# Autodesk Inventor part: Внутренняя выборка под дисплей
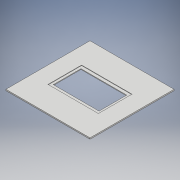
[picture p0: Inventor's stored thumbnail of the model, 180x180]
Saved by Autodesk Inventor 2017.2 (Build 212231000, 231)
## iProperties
Part Number: Внутренняя выборка под дисплей
Material: Типовые
Document SubType Name: Modeling
Designer: User
Density: 1 g/cm^3
Appearance: По умолчанию
Author: User
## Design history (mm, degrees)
sketch "Эскиз1"
  geometry: L1 (-100, -100)-(100, -100); L2 (100, -100)-(100, 100); L3 (100, 100)-(-100, 100); L4 (-100, 100)-(-100, -100); L5 (-100, -100)-(100, 100); L6 (100, -100)-(-100, 100); L7 (-54.5, -33)-(54.5, -33); L8 (54.5, -33)-(54.5, 33); L9 (54.5, 33)-(-54.5, 33); L10 (-54.5, 33)-(-54.5, -33); L11 (-54.5, -33)-(54.5, 33); L12 (54.5, -33)-(-54.5, 33); 1 further point
  constraints: 24 end point, 4 midpoint, 4 parallel, 2 horizontal, 2 perpendicular
  dimensions: "d0" = 200 distance of L3.end L2.end; "d1" = 200 distance of L2.end L1.end; "d2" = 109 distance of L9.end L8.end; "d3" = 66 distance of L8.end L7.end
extrude "Выдавливание1" new body sketch "Эскиз1" distance "d4" = 3; taper "d5" = 0 deg
sketch "Эскиз2"
  geometry: L1 (-60, -40)-(60, -40); L2 (60, -40)-(60, 40); L3 (60, 40)-(-60, 40); L4 (-60, 40)-(-60, -40); L5 (-60, -40)-(60, 40); L6 (60, -40)-(-60, 40); 1 further point
  constraints: 12 end point, 2 midpoint, 2 parallel, 1 horizontal, 1 perpendicular
  dimensions: "d6" = 120 distance of L3.end L2.end; "d7" = 80 distance of L2.end L1.end
extrude "Выдавливание2" cut sketch "Эскиз2" distance "d8" = 1.2; taper "d9" = 0 deg
node "Твердое тело1"
